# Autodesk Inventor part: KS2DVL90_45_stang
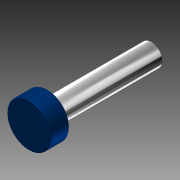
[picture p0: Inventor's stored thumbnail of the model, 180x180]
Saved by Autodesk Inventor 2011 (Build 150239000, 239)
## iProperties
Created: 2010-10
Document SubType Name: Modeling
Designer: TB
Mass: 161.233 g
Surface Area: 236.814 cm^2
Volume: 161.233 cm^3
Density: 1 g/cm^3
Author: TB
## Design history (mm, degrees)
sketch "Sketch2"
  geometry: L1 (-35, -3)-(-35, 3) reference; L2 (-35, -9)-(-35, 9) reference; L3 (-35, 22.5)-(-288, 22.5); L4 (-288, 22.5)-(-288, 0); L5 (-288, 0)-(-35, 0); L6 (-35, 0)-(-35, 22.5); L7 (-288, 22.5)-(-249, 22.5); L8 (-249, 22.5)-(-249, 45); L9 (-249, 45)-(-288, 45); L10 (-288, 45)-(-288, 22.5); 1 further point
  constraints: 16 end point, 4 parallel, 2 horizontal, 2 perpendicular, 1 midpoint
  dimensions: "Dia" = 45 diameter of L3 L5; "d3" = 253 distance of L3.start L3.end (computed from Slaglengde, Forlengelse_rør); "StempelDia" = 90 diameter of L9 L5; "StempelLengde" = 39 distance of L8.end L9.end
revolve "Revolution1" sketch "Sketch2" stored, may be unused: angle "d6" = 90 deg
fillet "Fillet1" dims "d7" = 2
sketch "Sketch3"
  geometry: L1 (-288, -43)-(-288, 43) reference; L2 (-288, 0)-(-288.01, 0); L3 (-288, 0)-(-288, 0.01); A1 r 0.01 centre (-288, 0) between (-288, 0.01) and (-288.01, 0); 1 further point
  constraints: 4 end point, 2 point on circle, 1 centre point, 1 midpoint, 1 perpendicular, 1 point on line
  dimensions: "d8" = 0.01 distance of L2.start L2.end; "d9" = 0.01 distance of L2.start L3.end (= d8); "d10" = 0.01 radius of A1 (= d8)
revolve "Revolution2" sketch "Sketch3" stored, may be unused: angle "d11" = 90 deg
body "Solid1"
node "Projected Loop2"
other parameters: "Forlengelse_rør" = 0
